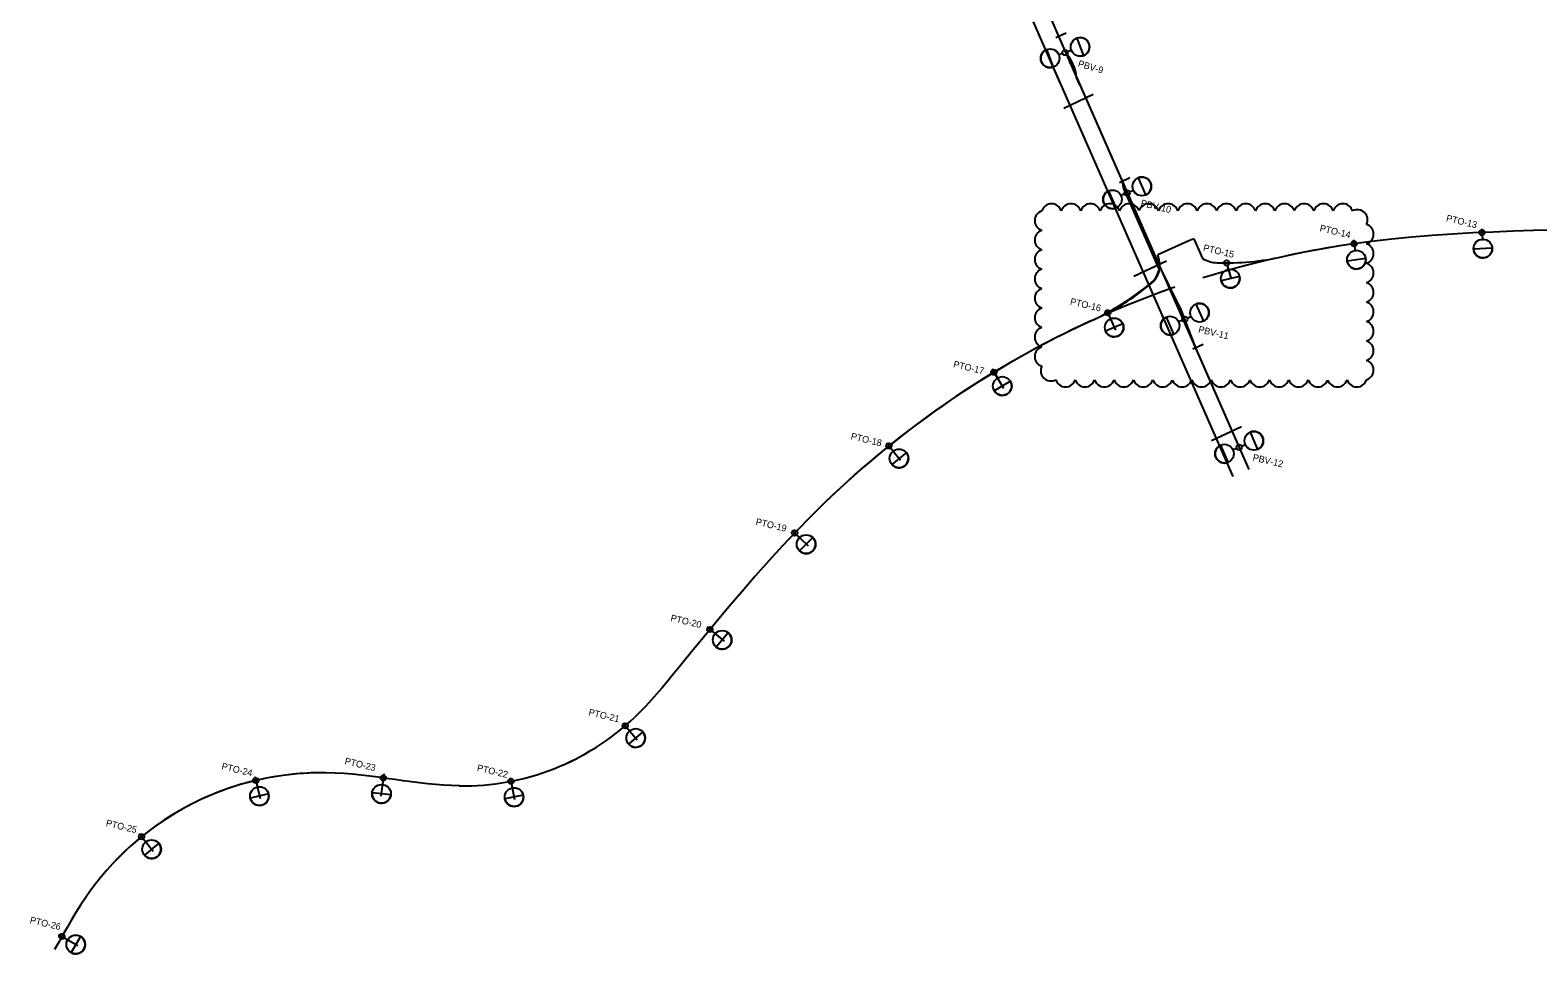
# Model space of a CAD drawing. Extents: x 0 to 511877, y 0 to 6211921.
# Drawn here: x 511372.6 to 511654.3, y 6211430.3 to 6211602.9 of the extents above; entities that cross this region are included whole.
import ezdxf

# ---------------------------------------------------------------- set-up
doc = ezdxf.new("R2010")
doc.units = 0
for name, color, linetype in [('Default', 7, 'Continuous'), ('Help', 7, 'Continuous'), ('TV_U_LYS_Ledn-', 7, 'Continuous'), ('TV_U_LYS_Ledn-ror', 7, 'Continuous'), ('TV_U_LYS_Mastenummer', 7, 'Continuous'), ('TV_U_LYS_Nyx330-Boligvej', 7, 'Continuous'), ('TV_U_LYS_Nyx330-Trafiksti', 7, 'Continuous')]:
    doc.layers.add(name, color=color, linetype=linetype)

msp = doc.modelspace()

# ---------------------------------------------------------------- linework, layer by layer
at = {"layer": 'Default'}
for centre, start, end in [((511563.44, 6211568.58), 17.5, 162.5), ((511567.07, 6211568.58), 17.5, 162.5), ((511570.7, 6211568.58), 17.5, 162.5), ((511574.33, 6211568.58), 17.5, 162.5), ((511577.96, 6211568.58), 17.5, 162.5), ((511581.59, 6211568.58), 17.5, 162.5), ((511585.22, 6211568.58), 17.5, 162.5), ((511588.84, 6211568.58), 17.5, 162.5), ((511592.47, 6211568.58), 17.5, 162.5), ((511596.1, 6211568.58), 17.5, 162.5), ((511599.73, 6211568.58), 17.5, 162.5), ((511603.36, 6211568.58), 17.5, 162.5), ((511606.99, 6211568.58), 17.5, 162.5), ((511610.62, 6211568.58), 17.5, 162.5), ((511614.25, 6211568.58), 17.5, 162.5), ((511617.88, 6211568.58), 17.5, 162.5), ((511562.2, 6211567.34), 107.5, 252.5), ((511620.6, 6211567.48), 333.3163, 118.3163), ((511562.2, 6211563.71), 107.5, 252.5), ((511621.72, 6211564.81), 287.5, 72.5), ((511621.72, 6211561.18), 287.5, 72.5), ((511562.2, 6211560.08), 107.5, 252.5), ((511621.72, 6211557.56), 287.5, 72.5), ((511562.2, 6211556.45), 107.5, 252.5), ((511562.2, 6211552.82), 107.5, 252.5), ((511621.72, 6211553.93), 287.5, 72.5), ((511562.2, 6211549.19), 107.5, 252.5), ((511621.72, 6211550.3), 287.5, 72.5), ((511621.72, 6211546.67), 287.5, 72.5), ((511562.2, 6211545.56), 107.5, 252.5), ((511562.2, 6211541.93), 107.5, 252.5), ((511621.72, 6211543.04), 287.5, 72.5), ((511563.32, 6211539.27), 153.3163, 298.3163), ((511621.72, 6211539.41), 287.5, 72.5), ((511566.04, 6211538.16), 197.5, 342.5), ((511569.67, 6211538.16), 197.5, 342.5), ((511573.3, 6211538.16), 197.5, 342.5), ((511576.93, 6211538.16), 197.5, 342.5), ((511580.56, 6211538.16), 197.5, 342.5), ((511584.19, 6211538.16), 197.5, 342.5), ((511587.82, 6211538.16), 197.5, 342.5), ((511591.45, 6211538.16), 197.5, 342.5), ((511595.08, 6211538.16), 197.5, 342.5), ((511598.7, 6211538.16), 197.5, 342.5), ((511602.33, 6211538.16), 197.5, 342.5), ((511605.96, 6211538.16), 197.5, 342.5), ((511609.59, 6211538.16), 197.5, 342.5), ((511613.22, 6211538.16), 197.5, 342.5), ((511616.85, 6211538.16), 197.5, 342.5), ((511620.48, 6211538.16), 197.5, 342.5)]:
    msp.add_arc(centre, 1.9, start, end, dxfattribs=at)
at = {"layer": 'Help'}
for p, q in [((511564.25, 6211601.54), (511566.17, 6211602.44)), ((511567.01, 6211596.57), (511600.31, 6211520.85)), ((511567.01, 6211596.57), (511600.31, 6211520.85)), ((511564.03, 6211595.26), (511597.33, 6211519.54)), ((511565.71, 6211588.37), (511571.22, 6211590.95)), ((511576.14, 6211574.48), (511578.06, 6211575.38)), ((511643.84, 6211565.82), (511643.94, 6211563.63)), ((511619.87, 6211563.72), (511620.19, 6211561.55)), ((511578.78, 6211556.95), (511584.91, 6211559.82)), ((511596.31, 6211558.74), (511596.92, 6211556.63)), ((511573.69, 6211550.69), (511575.36, 6211546.85)), ((511589.83, 6211543.36), (511591.75, 6211544.26)), ((511552.3, 6211539.63), (511554.47, 6211536.05)), ((511593.33, 6211526.22), (511598.96, 6211528.87)), ((511532.58, 6211525.81), (511535.21, 6211522.55)), ((511514.89, 6211509.47), (511517.94, 6211506.59)), ((511499.04, 6211491.4), (511502.26, 6211488.72)), ((511483.3, 6211473.49), (511485.99, 6211470.28)), ((511414.56, 6211463.43), (511415.53, 6211459.35)), ((511438.67, 6211463.92), (511438.09, 6211459.77)), ((511462.28, 6211463.29), (511463.05, 6211459.17)), ((511392.91, 6211452.77), (511395.55, 6211449.52)), ((511377.86, 6211433.94), (511381.49, 6211431.84))]:
    msp.add_line(p, q, dxfattribs=at)
for points in [[(511559.98, 6211604.48), (511564.93, 6211593.23)], [(511562.96, 6211605.78), (511567.9, 6211594.54)], [(511673.05, 6211566.5), (511671.58, 6211566.29), (511670.11, 6211566.13), (511668.63, 6211566.01), (511667.13, 6211565.91), (511665.61, 6211565.83), (511664.09, 6211565.77), (511662.55, 6211565.72), (511660.99, 6211565.68), (511657.24, 6211565.58), (511653.47, 6211565.47), (511649.71, 6211565.35), (511645.93, 6211565.2), (511642.15, 6211565.03), (511638.37, 6211564.82), (511634.58, 6211564.56), (511630.79, 6211564.25), (511627, 6211563.88), (511623.2, 6211563.45), (511619.43, 6211562.94), (511619.42, 6211562.94)], [(511521.16, 6211514.73), (511521.15, 6211514.72), (511518.44, 6211512.05), (511515.77, 6211509.32), (511513.16, 6211506.55), (511510.59, 6211503.74), (511508.07, 6211500.9), (511505.59, 6211498.04), (511503.14, 6211495.15), (511500.71, 6211492.26), (511498.31, 6211489.35), (511495.92, 6211486.45), (511493.54, 6211483.54), (511492.56, 6211482.33), (511491.58, 6211481.14), (511490.59, 6211479.97), (511489.61, 6211478.82), (511488.61, 6211477.7), (511487.6, 6211476.6), (511486.58, 6211475.54), (511485.52, 6211474.5)], [(511452.76, 6211461.69), (511451.28, 6211461.74), (511449.8, 6211461.82), (511448.32, 6211461.94), (511446.83, 6211462.09), (511445.32, 6211462.27), (511443.8, 6211462.46), (511442.28, 6211462.67), (511440.74, 6211462.89), (511439.18, 6211463.1), (511437.61, 6211463.32), (511436.03, 6211463.52), (511434.43, 6211463.71), (511432.82, 6211463.87), (511431.18, 6211464), (511429.54, 6211464.1), (511427.9, 6211464.15), (511427.88, 6211464.15)], [(511383.85, 6211442.16), (511383.84, 6211442.14), (511382.9, 6211440.8), (511381.98, 6211439.42), (511381.11, 6211438.04), (511380.27, 6211436.65), (511379.46, 6211435.26), (511378.67, 6211433.87), (511377.9, 6211432.49), (511377.14, 6211431.12)]]:
    msp.add_lwpolyline(points, dxfattribs=at)
for centre, radius, start, end in [((511629.94, 6211624.25), 72, 203.1682, 203.7372), ((511629.94, 6211624.25), 68.75, 203.1682, 203.7372), ((511645.09, 6211386.34), 178.45, 98.2732, 107.4), ((511645.09, 6211386.34), 178.45, 109.1784, 133.988), ((511453.44, 6211508.24), 46.55, 269.1662, 313.5533), ((511427.07, 6211410.7), 53.45, 89.135, 143.9525)]:
    msp.add_arc(centre, radius, start, end, dxfattribs=at)
at = {"layer": 'TV_U_LYS_Ledn-'}
for p, q in [((511568.69, 6211592.74), (511568.1, 6211594.09)), ((511568.69, 6211592.74), (511583.41, 6211559.27)), ((511576.64, 6211574.66), (511576.85, 6211573.34)), ((511576.85, 6211573.34), (511583.59, 6211558)), ((511590.04, 6211563.95), (511589.1, 6211563.54)), ((511590.04, 6211563.95), (511591.65, 6211560.28)), ((511587.43, 6211551.19), (511590.31, 6211543.59)), ((511590.31, 6211543.59), (511598.52, 6211524.92))]:
    msp.add_line(p, q, dxfattribs=at)
for points in [[(511562.96, 6211605.78), (511566.11, 6211598.63)], [(511673.05, 6211566.5), (511671.58, 6211566.29), (511670.11, 6211566.13), (511668.63, 6211566.01), (511667.13, 6211565.91), (511665.61, 6211565.83), (511664.09, 6211565.77), (511662.55, 6211565.72), (511660.99, 6211565.68), (511657.24, 6211565.58), (511653.47, 6211565.47), (511649.71, 6211565.35), (511645.93, 6211565.2), (511642.15, 6211565.03), (511638.37, 6211564.82), (511634.58, 6211564.56), (511630.79, 6211564.25), (511627, 6211563.88), (511623.2, 6211563.45), (511619.43, 6211562.94), (511619.42, 6211562.94)], [(511521.16, 6211514.73), (511521.15, 6211514.72), (511518.44, 6211512.05), (511515.77, 6211509.32), (511513.16, 6211506.55), (511510.59, 6211503.74), (511508.07, 6211500.9), (511505.59, 6211498.04), (511503.14, 6211495.15), (511500.71, 6211492.26), (511498.31, 6211489.35), (511495.92, 6211486.45), (511493.54, 6211483.54), (511492.56, 6211482.33), (511491.58, 6211481.14), (511490.59, 6211479.97), (511489.61, 6211478.82), (511488.61, 6211477.7), (511487.6, 6211476.6), (511486.58, 6211475.54), (511485.51, 6211474.5)], [(511452.77, 6211461.69), (511451.28, 6211461.74), (511449.8, 6211461.82), (511448.32, 6211461.94), (511446.83, 6211462.09), (511445.32, 6211462.27), (511443.8, 6211462.46), (511442.28, 6211462.67), (511440.74, 6211462.89), (511439.18, 6211463.1), (511437.61, 6211463.32), (511436.03, 6211463.52), (511434.43, 6211463.71), (511432.82, 6211463.87), (511431.18, 6211464), (511429.54, 6211464.1), (511427.9, 6211464.15), (511427.88, 6211464.15)]]:
    msp.add_lwpolyline(points, dxfattribs=at)
for centre, radius, start, end in [((511560.62, 6211593.51), 7.51, 4.4577, 43.0168), ((511645.09, 6211386.34), 178.45, 98.2732, 102.4444), ((511579.09, 6211559.17), 4.55, 310.0034, 23.354), ((511594.54, 6211565.01), 5.55, 238.834, 268.1545), ((511595.96, 6211608.99), 49.55, 268.1545, 282.4444), ((511579.09, 6211559.17), 4.65, 310.0034, 345.453), ((511550.16, 6211593.64), 49.55, 294.6059, 310.0034), ((511550.16, 6211593.64), 49.65, 298.6355, 310.0034), ((511645.09, 6211386.34), 178.45, 114.6059, 133.988), ((511453.44, 6211508.24), 46.55, 269.1619, 313.5576), ((511427.07, 6211410.7), 53.45, 89.135, 137.3284)]:
    msp.add_arc(centre, radius, start, end, dxfattribs=at)
at = {"layer": 'TV_U_LYS_Ledn-ror'}
for p, q in [((511589.1, 6211563.54), (511583.27, 6211560.97)), ((511587.43, 6211551.19), (511583.41, 6211559.27))]:
    msp.add_line(p, q, dxfattribs=at)
at = {"layer": 'TV_U_LYS_Nyx330-Boligvej'}
for p, q in [((511563.78, 6211596.04), (511562.54, 6211599.32)), ((511566.44, 6211598.92), (511567.14, 6211599.18)), ((511568.17, 6211601.44), (511569.4, 6211598.16)), ((511568.17, 6211601.44), (511568.17, 6211601.44)), ((511563.78, 6211596.04), (511563.78, 6211596.04)), ((511565.5, 6211598.56), (511564.8, 6211598.3)), ((511579.62, 6211575.33), (511581.02, 6211572.13)), ((511579.62, 6211575.33), (511579.62, 6211575.33)), ((511575.52, 6211569.71), (511574.12, 6211572.91)), ((511577.11, 6211572.32), (511576.42, 6211572.02)), ((511578.03, 6211572.72), (511578.72, 6211573.02)), ((511575.52, 6211569.71), (511575.52, 6211569.71)), ((511590.39, 6211551.73), (511591.8, 6211548.52)), ((511590.39, 6211551.73), (511590.39, 6211551.73)), ((511586.3, 6211546.11), (511584.89, 6211549.31)), ((511587.88, 6211548.72), (511587.2, 6211548.42)), ((511588.8, 6211549.12), (511589.49, 6211549.42)), ((511586.3, 6211546.11), (511586.3, 6211546.11)), ((511598.96, 6211525.19), (511599.65, 6211525.49)), ((511600.54, 6211527.8), (511601.95, 6211524.59)), ((511600.54, 6211527.8), (511600.54, 6211527.8)), ((511596.45, 6211522.17), (511595.04, 6211525.38)), ((511598.04, 6211524.78), (511597.35, 6211524.48)), ((511596.45, 6211522.17), (511596.45, 6211522.17))]:
    msp.add_line(p, q, dxfattribs=at)
for centre, radius in [((511568.78, 6211599.8), 1.75), ((511563.16, 6211597.68), 1.75), ((511565.97, 6211598.74), 0.5), ((511565.97, 6211598.74), 0.5), ((511580.32, 6211573.73), 1.75), ((511574.82, 6211571.31), 1.75), ((511577.57, 6211572.52), 0.5), ((511577.57, 6211572.52), 0.5), ((511591.09, 6211550.13), 1.75), ((511585.59, 6211547.71), 1.75), ((511588.34, 6211548.92), 0.5), ((511588.34, 6211548.92), 0.5), ((511595.75, 6211523.78), 1.75), ((511598.5, 6211524.98), 0.5), ((511598.5, 6211524.98), 0.5), ((511601.25, 6211526.19), 1.75)]:
    msp.add_circle(centre, radius, dxfattribs=at)
for centre, start, end in [((511568.78, 6211599.8), 290.6236, 110.5536), ((511563.16, 6211597.68), 110.6236, 290.5536), ((511580.32, 6211573.73), 293.7498, 113.6798), ((511574.82, 6211571.31), 113.7498, 293.6798), ((511591.09, 6211550.13), 293.7498, 113.6798), ((511585.59, 6211547.71), 113.7498, 293.6798), ((511601.25, 6211526.19), 293.7498, 113.6798), ((511595.75, 6211523.78), 113.7498, 293.6798)]:
    msp.add_arc(centre, 1.75, start, end, dxfattribs=at)
at = {"layer": 'TV_U_LYS_Nyx330-Trafiksti'}
for p, q in [((511620.05, 6211562.52), (511620.15, 6211561.77)), ((511645.79, 6211562.21), (511642.29, 6211562.01)), ((511643.9, 6211564.61), (511643.94, 6211563.86)), ((511645.79, 6211562.21), (511645.79, 6211562.21)), ((511622.14, 6211560.29), (511618.68, 6211559.79)), ((511622.14, 6211560.29), (511622.14, 6211560.29)), ((511598.54, 6211556.91), (511595.13, 6211556.11)), ((511596.26, 6211558.94), (511596.43, 6211558.21)), ((511598.54, 6211556.91), (511598.54, 6211556.91)), ((511576.74, 6211548.07), (511573.53, 6211546.67)), ((511574.14, 6211549.66), (511574.44, 6211548.97)), ((511576.74, 6211548.07), (511576.74, 6211548.07)), ((511555.74, 6211537.34), (511552.74, 6211535.52)), ((511552.94, 6211538.57), (511553.33, 6211537.93)), ((511555.74, 6211537.34), (511555.74, 6211537.34)), ((511533.36, 6211524.84), (511533.83, 6211524.26)), ((511536.3, 6211523.99), (511533.57, 6211521.79)), ((511536.3, 6211523.99), (511536.3, 6211523.99)), ((511515.79, 6211508.61), (511516.33, 6211508.08)), ((511518.8, 6211508.12), (511516.36, 6211505.61)), ((511518.8, 6211508.12), (511518.8, 6211508.12)), ((511499.99, 6211490.6), (511500.56, 6211490.11)), ((511503.03, 6211490.31), (511500.76, 6211487.64)), ((511503.03, 6211490.31), (511503.03, 6211490.31)), ((511484.1, 6211472.55), (511484.59, 6211471.97)), ((511487.06, 6211471.79), (511484.4, 6211469.51)), ((511487.06, 6211471.79), (511487.06, 6211471.79)), ((511414.84, 6211462.22), (511415.02, 6211461.49)), ((511438.51, 6211462.69), (511438.42, 6211461.94)), ((511462.52, 6211462.07), (511462.66, 6211461.33)), ((511417.12, 6211460.19), (511413.72, 6211459.38)), ((511417.12, 6211460.19), (511417.12, 6211460.19)), ((511439.96, 6211460), (511436.48, 6211460.41)), ((511439.96, 6211460), (511439.96, 6211460)), ((511464.72, 6211459.95), (511461.28, 6211459.28)), ((511464.72, 6211459.95), (511464.72, 6211459.95)), ((511393.69, 6211451.81), (511394.16, 6211451.22)), ((511396.63, 6211450.97), (511393.91, 6211448.76)), ((511396.63, 6211450.97), (511396.63, 6211450.97)), ((511378.93, 6211433.32), (511379.58, 6211432.94)), ((511381.98, 6211433.57), (511380.21, 6211430.54)), ((511381.98, 6211433.57), (511381.98, 6211433.57))]:
    msp.add_line(p, q, dxfattribs=at)
for centre, radius in [((511643.87, 6211565.11), 0.5), ((511619.97, 6211563.01), 0.5), ((511644.04, 6211562.11), 1.75), ((511596.15, 6211559.43), 0.5), ((511620.41, 6211560.04), 1.75), ((511596.84, 6211556.51), 1.75), ((511575.14, 6211547.37), 1.75), ((511573.94, 6211550.12), 0.5), ((511552.68, 6211539), 0.5), ((511554.24, 6211536.43), 1.75), ((511533.05, 6211525.23), 0.5), ((511534.93, 6211522.9), 1.75), ((511515.43, 6211508.96), 0.5), ((511517.58, 6211506.86), 1.75), ((511499.6, 6211490.92), 0.5), ((511501.89, 6211488.98), 1.75), ((511483.77, 6211472.92), 0.5), ((511485.73, 6211470.65), 1.75), ((511438.56, 6211463.19), 0.5), ((511415.42, 6211459.79), 1.75), ((511414.73, 6211462.71), 0.5), ((511438.22, 6211460.21), 1.75), ((511463, 6211459.61), 1.75), ((511462.42, 6211462.56), 0.5), ((511393.38, 6211452.2), 0.5), ((511395.27, 6211449.86), 1.75), ((511378.5, 6211433.57), 0.5), ((511381.09, 6211432.06), 1.75)]:
    msp.add_circle(centre, radius, dxfattribs=at)
for centre, start, end in [((511644.04, 6211562.11), 183.2609, 3.1909), ((511620.41, 6211560.04), 188.3251, 8.2552), ((511596.84, 6211556.51), 193.2798, 13.2099), ((511575.14, 6211547.37), 203.5313, 23.4614), ((511554.24, 6211536.43), 211.171, 31.1011), ((511534.93, 6211522.9), 218.9409, 38.8709), ((511517.58, 6211506.86), 225.7528, 45.6828), ((511501.89, 6211488.98), 229.6452, 49.5752), ((511485.73, 6211470.65), 220.6742, 40.6042), ((511415.42, 6211459.79), 193.3644, 13.2945), ((511438.22, 6211460.21), 173.3661, 353.2961), ((511463, 6211459.61), 191.134, 11.064), ((511395.27, 6211449.86), 219.0912, 39.0213), ((511381.09, 6211432.06), 239.7473, 59.6773)]:
    msp.add_arc(centre, 1.75, start, end, dxfattribs=at)

# ---------------------------------------------------------------- texts
at = {"layer": 'TV_U_LYS_Mastenummer'}
for s, rotation, p in [('PBV-9', 343.5084, (511568.27, 6211596.16)), ('PBV-10', 346.6346, (511580.01, 6211570.07)), ('PTO-13', 346.664, (511637.09, 6211567.25)), ('PTO-14', 346.664, (511613.46, 6211565.39)), ('PTO-15', 346.664, (511591.69, 6211561.72)), ('PTO-16', 346.664, (511566.82, 6211551.68)), ('PBV-11', 346.6346, (511590.78, 6211546.47)), ('PTO-17', 346.664, (511544.98, 6211539.96)), ('PTO-18', 346.664, (511525.84, 6211526.49)), ('PBV-12', 346.6346, (511600.94, 6211522.53)), ('PTO-19', 346.664, (511508.06, 6211510.52)), ('PTO-20', 346.664, (511492.15, 6211492.53)), ('PTO-21', 346.664, (511476.83, 6211474.91)), ('PTO-23', 346.664, (511431.26, 6211465.79)), ('PTO-24', 346.664, (511408.24, 6211464.81)), ('PTO-22', 346.664, (511455.98, 6211464.52)), ('PTO-25', 346.664, (511386.63, 6211454.2)), ('PTO-26', 346.664, (511372.43, 6211436.07))]:
    msp.add_text(s, height=1.25, rotation=rotation, dxfattribs=at).set_placement(p)

doc.saveas('drawing.dxf')
